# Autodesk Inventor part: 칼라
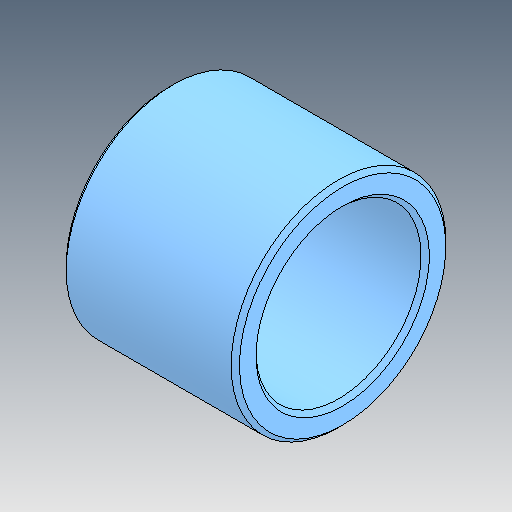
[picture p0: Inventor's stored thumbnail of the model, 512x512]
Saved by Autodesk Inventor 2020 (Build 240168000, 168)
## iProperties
Created: 2025-01
Part Number: 칼라
Material: 강철, 연강
Document SubType Name: Modeling
Designer: 1강의실14
Density: 7.85 g/cm^3
Appearance: 기본값
Author: jhkim
Sending System: Autodesk Inventor 2025
Preprocessor: ST-DEVELOPER v20
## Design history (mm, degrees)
feature "솔리드1"
node "솔리드2"
